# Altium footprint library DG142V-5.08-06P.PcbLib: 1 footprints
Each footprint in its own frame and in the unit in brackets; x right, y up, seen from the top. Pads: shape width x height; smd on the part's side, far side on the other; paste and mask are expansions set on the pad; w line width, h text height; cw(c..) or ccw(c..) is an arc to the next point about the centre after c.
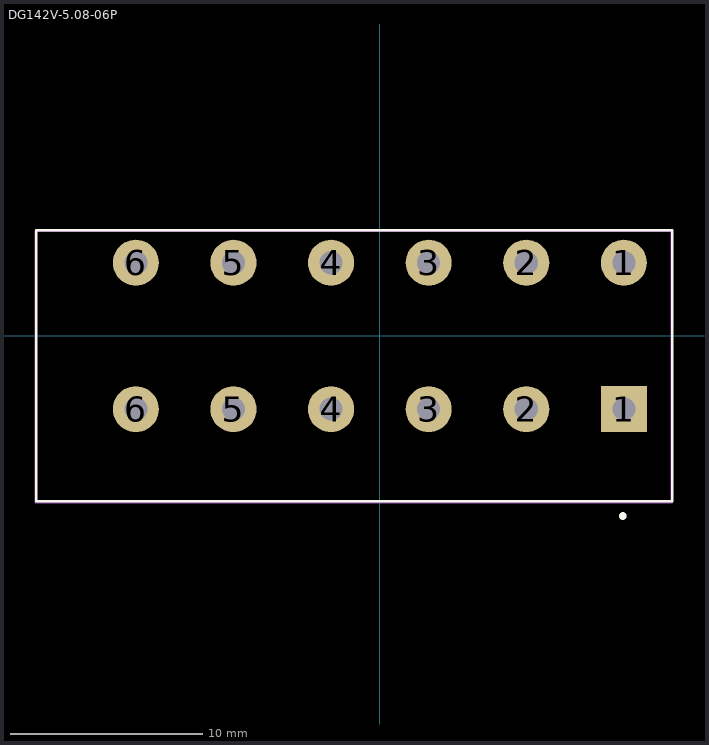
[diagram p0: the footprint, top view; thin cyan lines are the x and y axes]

## DG142V-5.08-06P [mm]
pads (12):
  rect 2.4x2.4 hole 1.2: 1(12.7,-3.81)
  round 2.4 hole 1.2: 1(12.7,3.81) 2(7.62,-3.81) 2(7.62,3.81) 3(2.54,-3.81) 3(2.54,3.81) 4(-2.54,-3.81) 4(-2.54,3.81) 5(-7.62,-3.81) 5(-7.62,3.81) 6(-12.7,-3.81) 6(-12.7,3.81)
Top Overlay:
  circle w0.2: c12.649,-9.373 r0.1
  lines w0.127: -17.882,-8.611 -17.882,5.512 15.215,5.512 15.215,-8.611 -17.882,-8.611
Mechanical 13:
  lines w0.127: -17.907,-8.661 15.189,-8.661 15.189,5.461 -17.907,5.461 -17.907,-8.661
3D body "DG142V-5.08-06P.stp": height 14.3, standoff -3.3, extent -17.886,-8.241 15.294,5.159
